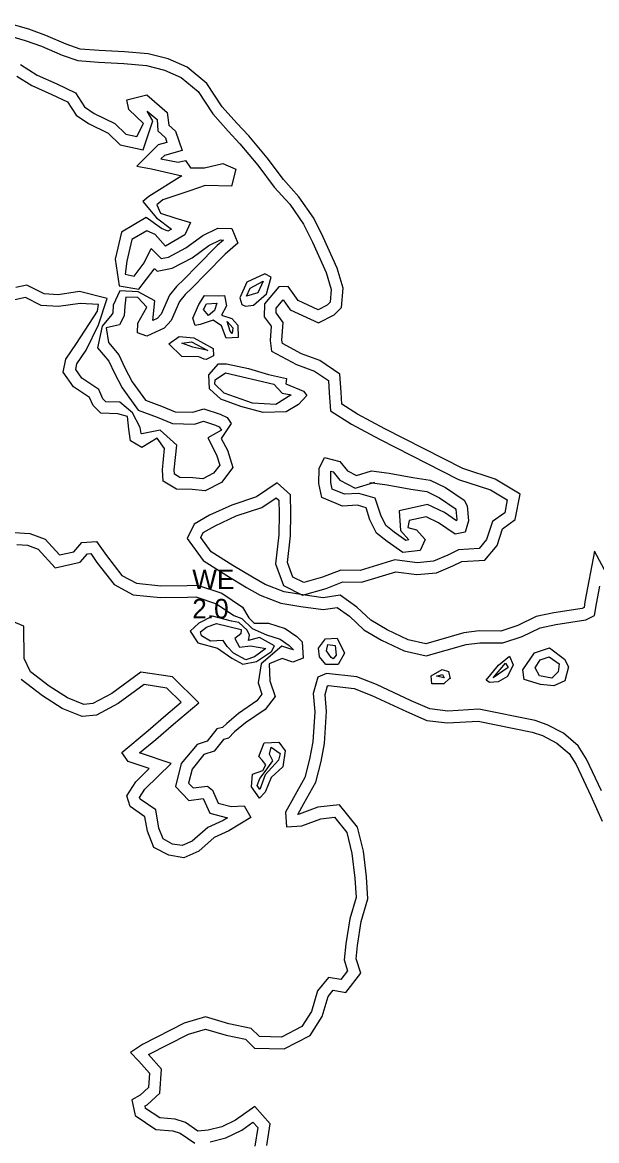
# Model space of a CAD drawing. Extents: x 2160437 to 2172832, y 205694 to 212444.
# Drawn here: x 2166011.6 to 2166158.2, y 208877.4 to 209162.8 of the extents above; entities that cross this region are included whole.
import ezdxf

# ---------------------------------------------------------------- set-up
doc = ezdxf.new("R2010")
doc.units = 0
for name, color, linetype in [('RD_EX_H2O', 7, 'Continuous'), ('RD_EX_H2O_Pond', 7, 'Continuous'), ('RD_EX_H2O_txCode', 7, 'Continuous'), ('RD_EX_VEG_ShrubLine', 7, 'Continuous'), ('RD_EX_VEG_TreeLine', 7, 'Continuous')]:
    doc.layers.add(name, color=color, linetype=linetype)

msp = doc.modelspace()

# ---------------------------------------------------------------- linework, layer by layer
at = {"layer": 'RD_EX_H2O'}
for points in [[(2166006.29, 209159.95), (2166012.34, 209158.19), (2166016.51, 209156.7), (2166021.72, 209154.41), (2166025.76, 209153.04), (2166031.02, 209152.65), (2166037.47, 209152.3), (2166043.26, 209151.8), (2166047.88, 209150.65), (2166052.11, 209148.77), (2166056.44, 209145.2), (2166060.24, 209139.43), (2166064.15, 209135.03), (2166067.15, 209131.82), (2166071.73, 209126.39), (2166075.93, 209120.77), (2166079.87, 209116.38), (2166083.41, 209111.3), (2166085.68, 209106.74), (2166089.15, 209098.99), (2166090.44, 209094.65), (2166090.21, 209091.39), (2166089.45, 209090.65), (2166087.15, 209089.47), (2166081.98, 209091.79), (2166079.47, 209095.36), (2166077.12, 209095.34), (2166073.44, 209090.98), (2166073.37, 209087.68), (2166075.1, 209085.31), (2166074.85, 209081.58), (2166075.22, 209078.92), (2166081.6, 209075.48), (2166086.21, 209073.79), (2166089.75, 209071.38), (2166089.97, 209068.25), (2166090.27, 209063.64), (2166095.67, 209060.24), (2166102.77, 209056.39), (2166122.93, 209046.14), (2166131.1, 209043.47), (2166135.39, 209040.91), (2166134.75, 209037.63), (2166131.65, 209035.42), (2166130.13, 209030.78), (2166128.23, 209028.49), (2166123, 209028.14), (2166120.24, 209026.83), (2166116.57, 209025.27), (2166112.4, 209024.9), (2166106.71, 209025.6), (2166097.81, 209022.91), (2166092.87, 209023), (2166088.19, 209021.17), (2166083.44, 209019.82), (2166080.65, 209021.23), (2166079.29, 209024.94), (2166080.09, 209031.79), (2166080.15, 209037.44), (2166080.03, 209042.18), (2166076.66, 209045.32), (2166071.36, 209041.67), (2166065.12, 209039.62), (2166059.4, 209036.99), (2166055.49, 209034.73), (2166053.7, 209031.09), (2166057.73, 209025.43), (2166063.79, 209021.59), (2166068.82, 209018.57), (2166072.32, 209016.6), (2166077.63, 209014.58), (2166082.73, 209013.72), (2166088.38, 209012.92), (2166091.96, 209013.47), (2166095.13, 209011.23), (2166098.75, 209007.79), (2166103.32, 209005.14), (2166109.08, 209002.39), (2166114.72, 209001.11), (2166124.91, 209004.06), (2166128.44, 209004.48), (2166134.24, 209004.43), (2166139.2, 209006.1), (2166143.78, 209008.27), (2166147.85, 209009.11), (2166155.46, 209010.33), (2166157.73, 209011.42), (2166158.2, 209014.42), (2166159.05, 209018.9)], [(2166011.14, 209152.06), (2166015.39, 209149.36), (2166020.39, 209147.11), (2166025.14, 209144.85), (2166027.49, 209141.27), (2166029.96, 209139.55), (2166035.24, 209137), (2166037.99, 209134.31), (2166040.84, 209133.69), (2166042.5, 209136.97), (2166038.77, 209140.57), (2166038.3, 209143.01), (2166043.33, 209144.29), (2166048.56, 209139.77), (2166048.98, 209136.57), (2166050.69, 209135.02), (2166052.43, 209130.09), (2166047.85, 209128.85), (2166046.98, 209127.99), (2166051.4, 209127.13), (2166053.22, 209127.58), (2166054.55, 209125.72), (2166058.06, 209125.64), (2166062.79, 209126.81), (2166066.14, 209125.3), (2166064.98, 209121.01), (2166058.31, 209121.14), (2166054.37, 209119.85), (2166047.43, 209117.51), (2166045.96, 209116.25), (2166046.85, 209114.1), (2166050.78, 209112.82), (2166054.5, 209111.74), (2166053.06, 209108.54), (2166048.12, 209105.72), (2166045.53, 209108.63), (2166043.38, 209109.6), (2166039.55, 209107.36), (2166038.25, 209101.82), (2166037.8, 209098.54), (2166040.1, 209098.04), (2166042.71, 209101.43), (2166044.47, 209105.08), (2166047, 209102.56), (2166048.9, 209102.91), (2166053.37, 209105.22), (2166057.67, 209108.39), (2166061.54, 209110.31), (2166065.08, 209110.16), (2166066.6, 209106.47), (2166063.41, 209103.64), (2166058.37, 209098.58), (2166055.02, 209095.17), (2166053.18, 209093.35), (2166051.73, 209091.6), (2166049.58, 209086.68), (2166047.8, 209084.72), (2166043.34, 209082.7), (2166041.03, 209083.57), (2166041.07, 209086.07), (2166043.39, 209090.13), (2166041.08, 209092.61), (2166038.04, 209092.66), (2166037.74, 209090.4), (2166037.62, 209087.87), (2166036.36, 209085.61), (2166032.96, 209084.86), (2166033.6, 209081.08), (2166036.23, 209077.98), (2166037.79, 209074.63), (2166039.62, 209071.1), (2166043.07, 209066.36), (2166047.08, 209064.86), (2166050.57, 209063.41), (2166055.09, 209063.3), (2166057.89, 209064.19), (2166062.07, 209062.79), (2166063.85, 209061.93), (2166064.91, 209060.43), (2166062.39, 209056.58), (2166063.94, 209053.6), (2166065.32, 209049.2), (2166062.41, 209045.4), (2166058.3, 209043.23), (2166054.98, 209043.58), (2166050.98, 209043.64), (2166047.54, 209045.73), (2166047.34, 209048.64), (2166047.91, 209054.03), (2166045.97, 209056.65), (2166042.09, 209054.31), (2166039.2, 209056.03), (2166038.74, 209059.01), (2166038.44, 209062.21), (2166035.98, 209062.89), (2166031.66, 209063.03), (2166029.67, 209065.01), (2166028.73, 209067.06), (2166024.62, 209069.81), (2166022.02, 209073.5), (2166022.69, 209076.87), (2166025.38, 209080.82), (2166030.78, 209089.08), (2166031, 209090.78), (2166026.33, 209091.09), (2166020.85, 209090.25), (2166016.35, 209090.54), (2166012.35, 209092.58), (2166008.14, 209091.65)], [(2166009.48, 209032.59), (2166013.53, 209032.38), (2166017.37, 209030.9), (2166021.04, 209026.9), (2166024.71, 209027.71), (2166026.79, 209030.08), (2166030.56, 209030.3), (2166033.03, 209026.73), (2166036.99, 209021.64), (2166040.77, 209019.63), (2166046.98, 209019), (2166053.69, 209019.1), (2166056.31, 209019.18), (2166062.52, 209017.11), (2166067.84, 209013.57), (2166069.42, 209010.81), (2166070.8, 209009.47), (2166074.4, 209009.47), (2166078.72, 209008.13), (2166081.7, 209006.06), (2166083.01, 209004.7), (2166083.27, 209000.49), (2166080.62, 208999.52), (2166077.96, 209000.42), (2166074.58, 208999.06), (2166074.8, 208994.75), (2166076.12, 208990.74), (2166073.55, 208987.45), (2166068.59, 208984.03), (2166065.79, 208981.69), (2166064.24, 208980.11), (2166062.95, 208979.78), (2166060.58, 208976.77), (2166057.96, 208975.9), (2166054.92, 208972.23), (2166054.04, 208968.66), (2166055.22, 208967.41), (2166058.85, 208967.87), (2166060.12, 208966.82), (2166061.63, 208963.5), (2166064.92, 208962.68), (2166068.2, 208962.88), (2166069.91, 208959.89), (2166064.29, 208956.47), (2166060.58, 208954.78), (2166056.61, 208951.28), (2166052.78, 208949.58), (2166048.98, 208950.22), (2166045.14, 208952.24), (2166043.5, 208956.34), (2166042.89, 208960.04), (2166039.08, 208962.66), (2166038.26, 208965.37), (2166040.54, 208968.97), (2166043.98, 208972.35), (2166038.59, 208974.12), (2166036.95, 208976.48), (2166043.69, 208982.09), (2166048.21, 208986), (2166052.17, 208989.33), (2166048.5, 208992.9), (2166042.65, 208993.79), (2166036.03, 208988.97), (2166030.49, 208986), (2166026.85, 208985.65), (2166021.76, 208987.7), (2166016.71, 208990.88), (2166011.27, 208995.07)], [(2166159.44, 208966.67), (2166155.62, 208974.79), (2166153.49, 208978.15), (2166149.75, 208981.37), (2166145.59, 208983.54), (2166142.54, 208984.58), (2166128.17, 208987.48), (2166120.25, 208987.03), (2166115.65, 208987.57), (2166110.89, 208989.65), (2166102.05, 208993.78), (2166097.02, 208995.75), (2166089.29, 208996.59), (2166087.03, 208995.65), (2166085.86, 208991.52), (2166086.26, 208986.87), (2166085.75, 208979.14), (2166084.92, 208974.76), (2166083.75, 208970.03), (2166080.86, 208964.88), (2166078.81, 208961.26), (2166079, 208957.49), (2166082.92, 208957.71), (2166087.77, 208959.54), (2166091.27, 208959.92), (2166094.46, 208956.05), (2166095.74, 208950.7), (2166096.51, 208944.4), (2166096.81, 208939.46), (2166095.18, 208933.98), (2166094.19, 208927.58), (2166093.79, 208923.49), (2166094.65, 208920.73), (2166092.91, 208918.48), (2166089.77, 208919.03), (2166086.98, 208915.65), (2166085.41, 208910.35), (2166082.98, 208906.49), (2166077.74, 208903.8), (2166072.12, 208903.93), (2166070.05, 208906.01), (2166064.33, 208907.23), (2166058.38, 208908.96), (2166052.9, 208907.34), (2166042.26, 208901.92), (2166039.23, 208899.92), (2166041.32, 208897.63), (2166044.04, 208894.6), (2166043.79, 208890.92), (2166041.67, 208889), (2166039.56, 208887.84), (2166040.36, 208883.76), (2166045.66, 208880.26), (2166050.01, 208879.92), (2166051.9, 208879.31), (2166055.59, 208876.75)], [(2166059.53, 208877.04), (2166063.55, 208878.09), (2166067.59, 208880.05), (2166070.46, 208882.1), (2166071.69, 208880.7), (2166070.99, 208875.94)]]:
    msp.add_lwpolyline(points, dxfattribs=at)
for points in [[(2166070.6, 209090.67), (2166073.96, 209093.52), (2166075.13, 209097.79), (2166073.48, 209098.6), (2166068.88, 209096.52), (2166067.11, 209092.52), (2166067.61, 209090.76), (2166068.54, 209090.37)], [(2166055.16, 209087.27), (2166056.62, 209090.84), (2166058.07, 209093.13), (2166061.66, 209093.02), (2166063.2, 209093.11), (2166063.69, 209090.46), (2166062.48, 209088.11), (2166065.08, 209087.21), (2166066.62, 209085.5), (2166066.66, 209082.39), (2166063.64, 209082.22), (2166062.4, 209085.33), (2166060.33, 209086.8), (2166056.99, 209085.72), (2166055.75, 209085.44)], [(2166056.62, 209077.45), (2166052.34, 209077.54), (2166048.96, 209080.77), (2166051.66, 209082.63), (2166055.34, 209082.26), (2166060.28, 209079.55), (2166060.39, 209077.67), (2166058.5, 209076.75), (2166058.04, 209076.86)], [(2166063.71, 209075.64), (2166069.32, 209074.43), (2166074.44, 209072.91), (2166079.02, 209071.95), (2166078.86, 209070.58), (2166083.37, 209068.67), (2166084.21, 209067.6), (2166082.08, 209065.26), (2166078.94, 209063.37), (2166073.04, 209063.2), (2166067.34, 209064.75), (2166062.29, 209066.6), (2166059.4, 209069.26), (2166059.2, 209072.83), (2166061.7, 209075.64)], [(2166100.73, 209048.34), (2166105.25, 209047.72), (2166111.31, 209046.61), (2166115.76, 209045.96), (2166119.63, 209044.09), (2166124.37, 209040.82), (2166125.17, 209039.44), (2166125.54, 209035.61), (2166124.69, 209032.65), (2166122.11, 209032.2), (2166117.86, 209035.1), (2166114.69, 209036.59), (2166110.39, 209035.64), (2166110.03, 209033.85), (2166112.22, 209033.31), (2166114.47, 209030.83), (2166113.21, 209028.03), (2166108.76, 209027.49), (2166104.76, 209030.28), (2166102.01, 209032.45), (2166100.36, 209035.86), (2166099.35, 209038.94), (2166097.19, 209039.55), (2166093.34, 209039.33), (2166088.04, 209041.5), (2166087.33, 209045.13), (2166087.38, 209048.92), (2166088.73, 209051.71), (2166092.68, 209050.74), (2166094.59, 209048.32), (2166096.88, 209047.13)], [(2166087.19, 209003.05), (2166088.96, 209005.5), (2166091.94, 209005.6), (2166093.89, 209001.78), (2166092.24, 208998.92), (2166089.1, 208998.89), (2166087.48, 209000.88)], [(2166139.37, 208997.51), (2166142.35, 209001.87), (2166146.17, 209003.16), (2166150.04, 209000.27), (2166151.01, 208998.28), (2166150.14, 208994.76), (2166147.33, 208993.45), (2166143.88, 208993.8), (2166139.73, 208995.12)], [(2166130.03, 208994.93), (2166133.14, 208998.75), (2166135.96, 209001.03), (2166136.94, 208998.79), (2166135.49, 208995.83), (2166133.07, 208994.46), (2166130.89, 208994.3)], [(2166119.21, 208993.98), (2166116.17, 208994.02), (2166115.94, 208996.05), (2166118.82, 208997.64), (2166120.38, 208997.11), (2166120.87, 208995.27), (2166120.67, 208995.36)], [(2166072, 208975.47), (2166073.31, 208978.9), (2166077.08, 208979.13), (2166078.66, 208976.91), (2166078.12, 208972.77), (2166075.16, 208970.08), (2166073.58, 208966.29), (2166072.12, 208964.78), (2166070.14, 208967.72), (2166070.32, 208970.94), (2166072.96, 208971.85), (2166073.73, 208973.31), (2166072.83, 208974.5)]]:
    msp.add_lwpolyline(points, close=True, dxfattribs=at)
at = {"layer": 'RD_EX_H2O_Pond'}
msp.add_lwpolyline([(2166058.63, 209008.47), (2166061.19, 209009.35), (2166067.48, 209007.84), (2166067.41, 209006.74), (2166065.81, 209005.59), (2166067, 209003.31), (2166069.88, 209003.7), (2166073.76, 209002.97), (2166070.9, 209000.9), (2166068.63, 209000.12), (2166065.5, 209001.83), (2166063.91, 209003.51), (2166062.86, 209005.06), (2166059.61, 209004.9), (2166057.37, 209006.21), (2166057.06, 209007.25)], close=True, dxfattribs=at)
at = {"layer": 'RD_EX_VEG_ShrubLine'}
for points in [[(2166163.95, 209016.08), (2166157.69, 209027.85), (2166155.25, 209014.93), (2166155.01, 209013.44), (2166154.56, 209013.23), (2166147.31, 209012.06), (2166142.82, 209011.13), (2166138.07, 209008.88), (2166133.76, 209007.43), (2166128.27, 209007.49), (2166124.31, 209007.01), (2166114.63, 209004.21), (2166110.07, 209005.24), (2166104.72, 209007.79), (2166100.56, 209010.21), (2166097.04, 209013.55), (2166092.71, 209016.61), (2166088.37, 209015.95), (2166083.19, 209016.68), (2166078.42, 209017.49), (2166073.6, 209019.33), (2166070.33, 209021.17), (2166065.36, 209024.15), (2166059.84, 209027.65), (2166057.19, 209031.37), (2166057.79, 209032.59), (2166060.78, 209034.33), (2166066.21, 209036.82), (2166072.7, 209038.95), (2166076.38, 209041.48), (2166077.06, 209040.85), (2166077.15, 209037.42), (2166077.09, 209031.98), (2166076.23, 209024.58), (2166078.25, 209019.09), (2166083.14, 209016.62), (2166089.15, 209018.32), (2166093.41, 209019.99), (2166098.22, 209019.9), (2166106.97, 209022.54), (2166112.35, 209021.88), (2166117.3, 209022.32), (2166121.47, 209024.09), (2166123.77, 209025.19), (2166129.71, 209025.58), (2166132.81, 209029.31), (2166134.19, 209033.55), (2166137.46, 209035.88), (2166138.73, 209042.41), (2166132.35, 209046.22), (2166124.08, 209048.92), (2166104.16, 209059.04), (2166097.19, 209062.83), (2166093.16, 209065.36), (2166092.96, 209068.45), (2166092.65, 209073.04), (2166087.59, 209076.48), (2166082.83, 209078.22), (2166077.98, 209080.84), (2166077.87, 209081.69), (2166078.16, 209086.2), (2166076.39, 209088.63), (2166076.42, 209089.86), (2166078.19, 209091.96), (2166080, 209089.4), (2166087.23, 209086.14), (2166091.23, 209088.19), (2166093.12, 209090.04), (2166093.48, 209094.98), (2166091.97, 209100.03), (2166088.39, 209108.02), (2166086, 209112.84), (2166082.22, 209118.25), (2166078.25, 209122.68), (2166074.08, 209128.25), (2166069.39, 209133.81), (2166066.37, 209137.05), (2166062.63, 209141.26), (2166058.7, 209147.23), (2166053.7, 209151.35), (2166048.85, 209153.5), (2166043.75, 209154.77), (2166037.69, 209155.29), (2166031.22, 209155.65), (2166026.36, 209156), (2166022.81, 209157.21), (2166017.62, 209159.49), (2166013.27, 209161.04), (2166007.18, 209162.81)], [(2166010.21, 209149.09), (2166013.97, 209146.71), (2166019.13, 209144.39), (2166023.09, 209142.5), (2166025.3, 209139.14), (2166028.44, 209136.96), (2166033.49, 209134.51), (2166036.52, 209131.57), (2166042.47, 209130.27), (2166044.87, 209137.67), (2166043.49, 209140.18), (2166046.01, 209137.98), (2166046.15, 209135.09), (2166048.11, 209133.31), (2166048.52, 209132.14), (2166046.3, 209131.54), (2166040.85, 209126.11), (2166044.58, 209125.39), (2166052.35, 209123.66), (2166043.86, 209118.4), (2166042.35, 209117.1), (2166045.86, 209112.95), (2166049.63, 209110.04), (2166048.75, 209109.53), (2166047.13, 209110.22), (2166043.2, 209112.97), (2166036.92, 209109.3), (2166035.3, 209102.37), (2166036.29, 209095.57), (2166041.32, 209094.71), (2166045.27, 209099.85), (2166045.34, 209099.98), (2166046, 209099.33), (2166049.88, 209100.04), (2166054.95, 209102.67), (2166059.24, 209105.82), (2166062.19, 209107.28), (2166062.96, 209107.25), (2166061.35, 209105.83), (2166056.23, 209100.69), (2166052.9, 209097.28), (2166050.97, 209095.38), (2166049.16, 209093.19), (2166047.03, 209088.34), (2166045.99, 209087.2), (2166044.88, 209086.7), (2166045.43, 209091.7), (2166041.17, 209094.04), (2166036.48, 209094.32), (2166034.75, 209090.66), (2166034.65, 209088.71), (2166034.4, 209088.25), (2166031.99, 209085.29), (2166030.78, 209079.77), (2166033.68, 209076.35), (2166035.09, 209073.31), (2166037.06, 209069.52), (2166041.18, 209063.87), (2166045.98, 209062.07), (2166049.94, 209060.42), (2166055.52, 209060.28), (2166057.87, 209061.04), (2166060.93, 209060.01), (2166061.85, 209059.57), (2166062.46, 209058.7), (2166062.46, 209058.7), (2166058.92, 209056.75), (2166061.15, 209052.46), (2166061.99, 209049.79), (2166060.42, 209047.75), (2166057.71, 209046.31), (2166055.16, 209046.58), (2166051.84, 209046.63), (2166050.43, 209047.49), (2166050.35, 209048.58), (2166051.02, 209054.88), (2166046.79, 209058.76), (2166042.08, 209057.81), (2166041.95, 209057.89), (2166041.71, 209059.38), (2166039.73, 209063.18), (2166036.44, 209065.88), (2166032.94, 209065.99), (2166032.17, 209066.76), (2166031.1, 209069.08), (2166026.75, 209071.99), (2166025.21, 209074.18), (2166025.51, 209075.68), (2166027.87, 209079.16), (2166030.99, 209085.65), (2166033.27, 209092.36), (2166026.2, 209094.1), (2166020.72, 209093.27), (2166017.16, 209093.49), (2166012.75, 209095.74), (2166009.92, 209095.12)], [(2166100.32, 209045.37), (2166104.78, 209044.75), (2166110.82, 209043.65), (2166114.87, 209043.06), (2166118.12, 209041.49), (2166122.11, 209038.74), (2166122.24, 209038.51), (2166122.5, 209035.88), (2166122.42, 209035.62), (2166119.36, 209037.71), (2166115.04, 209039.74), (2166107.83, 209038.15), (2166108.18, 209033.1), (2166110.29, 209030.7), (2166109.53, 209030.6), (2166106.55, 209032.69), (2166104.41, 209034.37), (2166103.15, 209036.99), (2166101.69, 209041.39), (2166097.52, 209042.57), (2166093.85, 209042.36), (2166090.67, 209043.67), (2166090.33, 209045.4), (2166090.37, 209048.21), (2166090.37, 209048.22), (2166090.96, 209048.07), (2166092.64, 209045.95), (2166096.6, 209043.9), (2166101.63, 209045.48)], [(2166010.18, 209029.55), (2166012.9, 209029.41), (2166015.63, 209028.35), (2166020, 209023.6), (2166026.31, 209024.99), (2166028.22, 209027.16), (2166029.05, 209027.21), (2166030.61, 209024.95), (2166035.02, 209019.29), (2166039.89, 209016.71), (2166046.85, 209016), (2166053.76, 209016.1), (2166055.87, 209016.17), (2166061.19, 209014.39), (2166065.59, 209011.46), (2166067.67, 209010.62), (2166070.23, 209008.14), (2166073.95, 209006.47), (2166077.39, 209005.4), (2166079.74, 209003.77), (2166080.84, 209002.62), (2166080.12, 209002.86), (2166077.86, 209003.62), (2166072.59, 208999.1), (2166071.83, 208994.2), (2166072.77, 208991.32), (2166071.47, 208989.65), (2166066.77, 208986.42), (2166063.76, 208983.89), (2166062.69, 208982.81), (2166061.23, 208982.45), (2166058.78, 208979.33), (2166056.2, 208978.48), (2166052.18, 208973.61), (2166050.73, 208967.79), (2166054.08, 208964.24), (2166057.78, 208964.71), (2166059.49, 208960.94), (2166064.01, 208959.81), (2166062.88, 208959.13), (2166058.93, 208957.32), (2166054.97, 208953.84), (2166052.38, 208952.69), (2166049.95, 208953.09), (2166047.52, 208954.38), (2166046.41, 208957.15), (2166045.64, 208961.8), (2166041.65, 208964.54), (2166041.53, 208964.93), (2166042.89, 208967.07), (2166049.61, 208973.66), (2166041.46, 208976.33), (2166045.63, 208979.81), (2166050.16, 208983.72), (2166056.64, 208989.16), (2166049.9, 208995.73), (2166041.88, 208996.95), (2166034.43, 208991.51), (2166029.6, 208988.93), (2166027.29, 208988.71), (2166023.13, 208990.39), (2166018.43, 208993.35), (2166013.67, 208997.01), (2166012.04, 209000.43), (2166011.97, 209008.69), (2166007.24, 209010.64)], [(2166074.05, 208876.11), (2166074.86, 208881.64), (2166070.92, 208886.1), (2166066.05, 208882.64), (2166062.5, 208880.92), (2166059.04, 208880.02), (2166056.42, 208879.82), (2166053.25, 208882.03), (2166050.6, 208882.89), (2166046.67, 208883.19), (2166043.06, 208885.57), (2166042.92, 208886.26), (2166043.42, 208886.53), (2166046.71, 208889.51), (2166047.12, 208895.66), (2166043.81, 208899.34), (2166054.02, 208904.54), (2166058.39, 208905.83), (2166063.6, 208904.32), (2166068.56, 208903.26), (2166070.85, 208900.96), (2166078.44, 208900.79), (2166085.08, 208904.2), (2166088.17, 208909.1), (2166089.69, 208914.21), (2166090.97, 208915.77), (2166094.19, 208915.21), (2166097.98, 208920.14), (2166096.83, 208923.8), (2166097.17, 208927.2), (2166098.11, 208933.32), (2166099.83, 208939.11), (2166099.5, 208944.68), (2166098.7, 208951.23), (2166097.21, 208957.42), (2166092.56, 208963.07), (2166087.07, 208962.49), (2166082.29, 208960.67), (2166081.92, 208960.65), (2166083.48, 208963.4), (2166086.57, 208968.92), (2166087.86, 208974.12), (2166088.73, 208978.76), (2166089.27, 208986.9), (2166088.9, 208991.23), (2166089.52, 208993.44), (2166089.73, 208993.52), (2166096.3, 208992.81), (2166100.87, 208991.02), (2166109.65, 208986.92), (2166114.86, 208984.64), (2166120.16, 208984.02), (2166127.96, 208984.47), (2166141.76, 208981.68), (2166144.4, 208980.78), (2166148.05, 208978.87), (2166151.2, 208976.17), (2166152.98, 208973.35), (2166156.71, 208965.41), (2166159.66, 208958.96)]]:
    msp.add_lwpolyline(points, dxfattribs=at)
for points in [[(2166068.81, 209092.89), (2166069.75, 209094.96), (2166073.06, 209096.79), (2166071.69, 209093.75)], [(2166057.83, 209089.52), (2166058.65, 209090.98), (2166061.22, 209091.15), (2166060.69, 209089.23), (2166059.11, 209087.95)], [(2166063.92, 209086.45), (2166065.34, 209084.81), (2166065.19, 209083.38), (2166064.63, 209083.97)], [(2166052.27, 209080.89), (2166054.77, 209081.26), (2166058.93, 209079.05), (2166055.16, 209079.92)], [(2166063.5, 209073.34), (2166075.82, 209070.45), (2166077.94, 209068.16), (2166080.27, 209067.78), (2166076.3, 209065.25), (2166070.32, 209065.61), (2166063.16, 209068.17), (2166060.7, 209070.45), (2166060.86, 209071.54)], [(2166065.03, 209009.98), (2166060.1, 209011.21), (2166056.65, 209009.44), (2166054.42, 209007.45), (2166056.37, 209004.41), (2166061.44, 209003.12), (2166065.08, 209000.49), (2166067.91, 208999.04), (2166071.35, 208999.66), (2166075.18, 209002.25), (2166076, 209003.71), (2166072.12, 209005.79), (2166069.3, 209005.07), (2166069.58, 209006.44), (2166068.99, 209007.7), (2166066.88, 209009.65)], [(2166089.21, 209002.42), (2166089.61, 209004.06), (2166091.46, 209003.73), (2166091.69, 209001.3), (2166090.92, 209000.32), (2166090.43, 209000.7)], [(2166131.8, 208995.53), (2166134.97, 208999.26), (2166135.63, 208998.13)], [(2166117.34, 208995.9), (2166118.88, 208996.36), (2166119.32, 208995.5)], [(2166074.67, 208976.05), (2166075.14, 208977.83), (2166077.38, 208976.16), (2166076.97, 208974.52), (2166073.6, 208970.72), (2166072.26, 208967), (2166071.54, 208967.99), (2166072.21, 208969.85), (2166073.82, 208971.95), (2166075.56, 208974.32)]]:
    msp.add_lwpolyline(points, close=True, dxfattribs=at)
at = {"layer": 'RD_EX_VEG_TreeLine'}
msp.add_lwpolyline([(2166142.51, 208998.02), (2166143.78, 209000.11), (2166146.12, 209000.89), (2166148.64, 208999.09), (2166148.38, 208997.04), (2166146.82, 208995.42), (2166143.61, 208996.03)], close=True, dxfattribs=at)

# ---------------------------------------------------------------- texts
at = {"layer": 'RD_EX_H2O_txCode'}
for s, p in [('WE', (2166054.97, 209018.16)), ('2.0', (2166054.97, 209010.66))]:
    msp.add_text(s, height=5, dxfattribs=at).set_placement(p)

doc.saveas('drawing.dxf')
